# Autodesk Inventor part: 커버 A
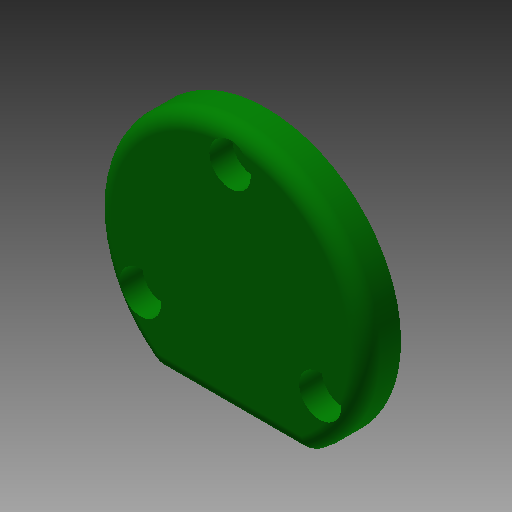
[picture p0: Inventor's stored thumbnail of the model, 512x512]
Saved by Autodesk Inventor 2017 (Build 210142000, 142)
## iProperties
Created: 2020-04
Part Number: 커버 A
Material: 알루미늄 6061
Document SubType Name: Modeling
Designer: mduedu
Density: 2.71 g/cm^3
Mass: 33.9278 g
Surface Area: 60.2978 cm^2
Volume: 12.5195 cm^3
Appearance: 진녹색
Author: mduedu
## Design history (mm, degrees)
sketch "스케치1"
  geometry: C1 r 26 at (0, 0); 1 further point
  constraints: 1 centre point, 1 coincident
  dimensions: "d0" = 52 diameter of C1
extrude "돌출1" new body sketch "스케치1" distance "d1" = 7; taper "d2" = 0 deg
sketch "스케치2"
  geometry: L1 (-14.62, -21.5)-(14.62, -21.5); A1 r 26 centre (0, 0) between (-14.62, -21.5) and (14.62, -21.5) reference; 1 further point
  constraints: 2 end point, 2 point on circle, 1 horizontal
  dimensions: "d3" = 21.5 distance from line of L1 point (0, 0)
extrude "돌출2" cut sketch "스케치2" stored distance "d4" = 7; taper "d5" = 0 deg
fillet "모깎기1" dims "d6" = 3
fillet "모깎기2" dims "d7" = 3
sketch "스케치3" dims "d8" = 40
  geometry: 3 further points
  constraints: 2 vertical alignment, 1 coincident, 2 other
hole "구멍1" sketch "스케치3" at (0, 20) diameter "d9" = 4.5; stored, may be unused: countersink angle "d13" = 90 deg, drill point angle "d15" = 118 deg; dims "d10" = 6, "d11" = 8, "d12" = 4.4, "d14" = 8
sketch "스케치4"
  geometry: C1 r 16 at (0, 0); 1 further point
  constraints: 1 centre point, 1 coincident
  dimensions: "d19" = 32 diameter of C1
extrude "돌출3" join sketch "스케치4" distance "d20" = 3; taper "d21" = 0 deg
sketch "스케치5"
  geometry: C1 r 14 at (0, 0); 1 further point
  constraints: 1 centre point, 1 coincident
  dimensions: "d22" = 28 diameter of C1
extrude "돌출4" cut sketch "스케치5" distance "d23" = 7; taper "d24" = 0 deg
fillet "모깎기3" dims "d25" = 3
chamfer "모따기1" distance "d26" = 0.5; stored, may be unused: second distance "d27" = 2, angle "d28" = 45 deg
node "솔리드1"
pattern_circular "원형 패턴1" dims angle "d17" = 360 deg
node "투영된 루프1"
